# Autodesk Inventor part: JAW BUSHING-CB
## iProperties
Created: 2006-07
Part Number: JAW BUSHING-CB
Material: Steel
Document SubType Name: Modeling
Designer: rollin42
Density: 7.85 g/cm^3
Stock Number: JAW BUSHING-CB
Author: rollin42
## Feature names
1. Extrusion1
2. Extrusion2
3. Hole1
4. Extrusion3
